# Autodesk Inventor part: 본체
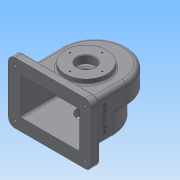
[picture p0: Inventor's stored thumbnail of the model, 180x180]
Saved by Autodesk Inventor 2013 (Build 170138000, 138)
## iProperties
Created: 2017-11
Part Number: 본체
Material: 일반
Document SubType Name: Modeling
Designer: Administrator
Density: 1 g/cm^3
Author: Administrator
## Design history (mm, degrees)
sketch "스케치1"
  geometry: L1 (-58, 0)-(-58, -80); L2 (-58, -80)-(58, -80); L3 (58, -80)-(58, 0); A1 r 58 centre (0, 0) between (58, 0) and (-58, 0); 1 further point
  constraints: 6 end point, 2 point on circle, 2 tangent, 1 centre point, 1 coincident, 1 parallel, 1 perpendicular, 1 vertical
  dimensions: "d0" = 116 diameter of A1; "d1" = 80 distance from line of L2 A1.centre
extrude "돌출1" new body sketch "스케치1" distance "d2" = 38; taper "d3" = 0 deg
sketch "스케치2"
  geometry: L1 (-58, 0)-(-58, -80) reference; L2 (-58, -80)-(58, -80) reference; L3 (58, -80)-(58, 0) reference; L4 (-58, -23)-(-58, -80); L5 (58, -80)-(58, -23); L6 (58, -80)-(-58, -80); A1 r 58 centre (0, 0) between (58, 0) and (-58, 0) reference; A2 r 58 centre (0, -23) between (58, -23) and (-58, -23)
  constraints: 6 end point, 3 collinear, 2 point on circle, 2 point on line, 1 centre point, 1 vertical alignment
  dimensions: "d4" = 116 diameter of A2; "d5" = 57 distance from line of L2 A2.centre
extrude "돌출2" join sketch "스케치2" distance "d6" = 38; taper "d7" = 0 deg
feature "쉘1" dims "d10" = 5
fillet "모깎기3" dims "d11" = 8
fillet "모깎기4" dims "d12" = 3
sketch "스케치3"
  geometry: L1 (108, -8)-(108, -68) reference; L2 (0, 0)-(100, 0) reference; L3 (-8, -8)-(-8, -68) reference; L4 (100, -76)-(0, -76) reference; L5 (-25, 17)-(125, 17); L6 (125, 17)-(125, -93); L7 (125, -93)-(-25, -93); L8 (-25, -93)-(-25, 17); L9 (-25, 17)-(125, -93); L10 (125, 17)-(-25, -93); A1 r 8 centre (100, -68) between (100, -76) and (108, -68) reference; A2 r 8 centre (100, -8) between (108, -8) and (100, 0) reference; A3 r 8 centre (0, -8) between (0, 0) and (-8, -8) reference; A4 r 8 centre (0, -68) between (-8, -68) and (0, -76) reference; 1 further point
  constraints: 12 end point, 2 midpoint, 2 parallel, 1 horizontal, 1 perpendicular
  dimensions: "d13" = 150 distance of L6.end L7.end; "d14" = 110 distance of L5.end L6.end
extrude "돌출3" join sketch "스케치3" distance "d15" = 15; taper "d16" = 0 deg
fillet "모깎기5" dims "d17" = 12
fillet "모깎기6" dims "d18" = 3
sketch "스케치4"
  geometry: A1 r 9 centre (113, -5) between (113, -14) and (122, -5) reference; A2 r 9 centre (113, 81) between (122, 81) and (113, 90) reference; A3 r 9 centre (-13, 81) between (-13, 90) and (-22, 81) reference; A4 r 9 centre (-13, -5) between (-22, -5) and (-13, -14) reference; 5 further points
  constraints: 4 coincident
hole "구멍1" sketch "스케치4" at (-13, 81), (-13, -5), (113, -5), (113, 81) diameter "d19" = 5; stored, may be unused: countersink angle "d23" = 90 deg, drill point angle "d25" = 118 deg; dims "d20" = 6, "d21" = 12, "d22" = 5, "d24" = 8
sketch "스케치5"
  geometry: L1 (-63, -80)-(63, -80) reference; C1 r 37.5 at (0, -15); A1 r 50 centre (0, 0) between (50, 0) and (-50, 0) reference
  constraints: 1 centre point, 1 vertical alignment
  dimensions: "d26" = 75 diameter of C1; "d27" = 65 distance from line of L1 C1.centre
extrude "돌출4" join sketch "스케치5" distance "d28" = 9; taper "d29" = 0 deg
sketch "스케치7"
  geometry: L1 (-63, -80)-(63, -80) reference; C1 r 31 at (0, -15); 1 further point
  constraints: 1 centre point, 1 vertical alignment
  dimensions: "d30" = 62 diameter of C1; "d31" = 65 distance from line of L1 C1.centre
extrude "돌출5" join sketch "스케치7" distance "d32" = 10; taper "d33" = 0 deg
sketch "스케치8"
  geometry: C1 r 31 at (0, 0) reference; C2 r 16 at (0, 0); 1 further point
  constraints: 1 centre point, 1 coincident
  dimensions: "d34" = 32 diameter of C2
extrude "돌출6" cut sketch "스케치8" stored distance "d35" = 10; taper "d36" = 0 deg
sketch "스케치9"
  geometry: C1 r 16 at (0, 0) reference; 2 further points
  constraints: 1 vertical alignment
  dimensions: "d37" = 29 distance of C1.centre point (0, 29)
hole "구멍2" sketch "스케치9" at (0, 29) diameter "d38" = 2.459; stored, may be unused: countersink angle "d42" = 90 deg, drill point angle "d44" = 118 deg; dims "d39" = 6, "d40" = 12, "d41" = 5, "d43" = 8
sketch "스케치10"
  geometry: C1 r 16 at (0, 0) reference; 2 further points
  constraints: 1 vertical alignment
  dimensions: "d48" = 26 distance of C1.centre point (0, 26)
hole "구멍3" sketch "스케치10" at (0, 26) diameter "d49" = 2.459; stored, may be unused: countersink angle "d53" = 90 deg, drill point angle "d55" = 118 deg; dims "d50" = 6, "d51" = 12, "d52" = 5, "d54" = 8
fillet "모깎기7" dims "d59" = 3
chamfer "모따기1" distance "d60" = 1; stored, may be unused: second distance "d61" = 2, angle "d62" = 45 deg
node "작업 평면1"
sketch "스케치11"
  geometry: L1 (-113, 93)-(-13, 93) reference; C1 r 6 at (-63, 74); 1 further point
  constraints: 1 centre point, 1 vertical alignment
  dimensions: "d64" = 12 diameter of C1; "d65" = 19 distance from line of L1 C1.centre
extrude "돌출7" join sketch "스케치11" stored distance "d66" = 10; taper "d67" = 0 deg
sketch "스케치12"
  geometry: C1 r 6 at (0, 0) reference; 2 further points
  constraints: 1 coincident
hole "구멍4" sketch "스케치12" at (0, 0) diameter "d68" = 4.459; stored, may be unused: countersink angle "d72" = 90 deg, drill point angle "d74" = 118 deg; dims "d69" = 6, "d70" = 12, "d71" = 5, "d73" = 8
fillet "모깎기8" dims "d75" = 3
sketch "스케치13"
  geometry: L1 (-35, 23)-(-35, -39) reference; L2 (-40, -57)-(-52, -57) reference; 2 further points
  constraints: 1 other
  dimensions: "d76" = 38 distance from line of L1 point (3, -17); "d77" = 40 distance from line of L2 point (3, -17)
feature "엠보싱1" sketch "스케치13" dims "d78" = 0.5, "d79" = 0
node "솔리드1"
pattern_circular "원형 패턴1" dims angle "d46" = 360 deg
pattern_circular "원형 패턴2" dims angle "d57" = 360 deg
other parameters: "d63" = -144
